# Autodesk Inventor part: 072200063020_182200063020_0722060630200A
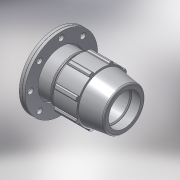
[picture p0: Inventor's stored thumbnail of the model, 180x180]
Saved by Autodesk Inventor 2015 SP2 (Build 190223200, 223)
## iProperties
Created: 2017-02
Part Number: 072200063020_182200063020_0722060630200A
Material: PVC-Piping
Description: PLASSON COMPRESSION FLANGE ADAPTOR 63-2"
Document SubType Name: Modeling
Designer: KIM
Mass: 92.6774 g
Surface Area: 199.44 cm^2
Volume: 66.1981 cm^3
Density: 1.4 g/cm^3
Appearance: Smooth - White
Author: KIM
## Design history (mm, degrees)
derived "07220.ipt"
feature "Solid1::07220.ipt"
tag "TaggingFeature1"
body "Solid1"
other parameters: "d2" = 63, "d4" = 20.71429, "d5" = 46.4, "d7" = 113, "d9" = 20.71429, "d11" = 4.14286, "d12" = 90.4, "d13" = 120 deg, "d14" = 81.9, "d15" = 12 deg, "d18" = 3.15, "d19" = 35 deg, "d20" = 17.5 deg, "d21" = 105.09, "d23" = 0, "d25" = 360 deg, "d27" = 2.26, "d42" = 50.75, "d43" = 3.39, "d46" = 1.89, "d53" = 1.26, "d67" = 5.65, "d70" = 145, "d71" = 165, "d73" = 12.08333, "d74" = 90 deg, "d75" = 0.3, "d76" = 165, "d77" = 18, "d78" = 62.5, "d80" = 0, "d82" = 360 deg, "d85" = 96.05, "d86" = 90.4, "d87" = 0.825, "d93" = 7.25, "d95" = 56.7, "d96" = 0.3, "d99" = 360 deg, "d_" = 63, "E_" = 113, "H_" = 145, "D_" = 165, "Dp_" = 125, "S_" = 18
